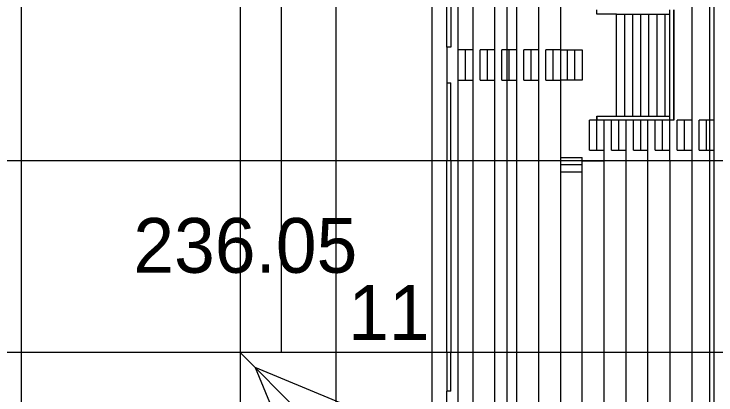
# Model space of a CAD drawing. Extents: x -264165 to -263575, y -1242333 to -1242036.
# Drawn here: x -263827.72 to -263802.08, y -1242218.43 to -1242204.52 of the extents above; entities that cross this region are included whole.
import ezdxf

# ---------------------------------------------------------------- set-up
doc = ezdxf.new("R2010")
doc.units = 0
for name, color, linetype in [('KFA_BODY_VYTYCOVAK', 7, 'Continuous'), ('KFA_HESCON_OSI_STAVBY', 7, 'Continuous'), ('KFA_SITUACIA_DRS_VYTYCOVAK_SEDA', 7, 'Continuous')]:
    doc.layers.add(name, color=color, linetype=linetype)

msp = doc.modelspace()

# ---------------------------------------------------------------- linework, layer by layer
at = {"layer": 'KFA_HESCON_OSI_STAVBY'}
for p, q in [((-263827.468, -1242080.447), (-263827.468, -1242248.737)), ((-263819.468, -1242080.447), (-263819.468, -1242248.737)), ((-263812.468, -1242080.447), (-263812.468, -1242248.737)), ((-263811.518, -1242080.447), (-263811.518, -1242248.737)), ((-263809.718, -1242080.447), (-263809.718, -1242248.737)), ((-263802.318, -1242080.447), (-263802.318, -1242248.737)), ((-263787.486, -1242209.882), (-263921.823, -1242209.882)), ((-263787.486, -1242216.882), (-263921.823, -1242216.882)), ((-263819.468, -1242216.882), (-263819.468, -1242216.882)), ((-263819.468, -1242216.882), (-263794.893, -1242241.457)), ((-263794.893, -1242227.382), (-263818.92, -1242217.43)), ((-263818.92, -1242217.43), (-263808.968, -1242241.457))]:
    msp.add_line(p, q, dxfattribs=at)
at = {"layer": 'KFA_SITUACIA_DRS_VYTYCOVAK_SEDA'}
for p, q in [((-263815.968, -1242108.382), (-263815.968, -1242220.382)), ((-263817.968, -1242111.882), (-263817.968, -1242216.882)), ((-263811.918, -1242205.732), (-263811.918, -1242202.882)), ((-263811.918, -1242205.732), (-263811.918, -1242202.882)), ((-263811.768, -1242202.882), (-263811.768, -1242205.732)), ((-263811.768, -1242202.882), (-263811.768, -1242205.732)), ((-263810.968, -1242202.882), (-263810.968, -1242209.882)), ((-263810.968, -1242202.882), (-263810.968, -1242209.882)), ((-263810.168, -1242202.882), (-263810.168, -1242209.882)), ((-263810.168, -1242202.882), (-263810.168, -1242209.882)), ((-263809.368, -1242202.882), (-263809.368, -1242209.882)), ((-263809.368, -1242202.882), (-263809.368, -1242209.882)), ((-263808.568, -1242202.882), (-263808.568, -1242209.882)), ((-263808.568, -1242202.882), (-263808.568, -1242209.882)), ((-263807.768, -1242202.882), (-263807.768, -1242209.882)), ((-263807.768, -1242202.882), (-263807.768, -1242209.882)), ((-263802.968, -1242202.882), (-263802.968, -1242209.882)), ((-263802.968, -1242202.882), (-263802.968, -1242209.882)), ((-263802.168, -1242202.882), (-263802.168, -1242209.882)), ((-263802.168, -1242202.882), (-263802.168, -1242209.882)), ((-263807.768, -1242203.003), (-263807.768, -1242205.832)), ((-263807.768, -1242203.003), (-263807.768, -1242205.832)), ((-263806.434, -1242204.52), (-263806.434, -1242204.37)), ((-263806.434, -1242204.52), (-263806.434, -1242204.37)), ((-263803.768, -1242208.394), (-263803.768, -1242204.369)), ((-263803.768, -1242208.394), (-263803.768, -1242204.369)), ((-263803.618, -1242208.394), (-263803.618, -1242204.369)), ((-263803.618, -1242208.394), (-263803.618, -1242204.369)), ((-263803.618, -1242204.369), (-263803.618, -1242208.394)), ((-263803.618, -1242204.369), (-263803.618, -1242208.394)), ((-263805.723, -1242204.52), (-263806.434, -1242204.52)), ((-263805.723, -1242204.52), (-263806.434, -1242204.52)), ((-263805.723, -1242208.245), (-263805.723, -1242204.52)), ((-263805.723, -1242208.245), (-263805.723, -1242204.52)), ((-263805.723, -1242204.52), (-263805.428, -1242204.52)), ((-263805.723, -1242204.52), (-263805.428, -1242204.52)), ((-263805.428, -1242204.52), (-263805.428, -1242208.245)), ((-263805.428, -1242204.52), (-263805.428, -1242208.245)), ((-263805.428, -1242204.52), (-263805.133, -1242204.52)), ((-263805.428, -1242204.52), (-263805.133, -1242204.52)), ((-263805.133, -1242204.52), (-263804.838, -1242204.52)), ((-263805.133, -1242204.52), (-263804.838, -1242204.52)), ((-263805.133, -1242204.52), (-263805.133, -1242208.245)), ((-263805.133, -1242204.52), (-263805.133, -1242208.245)), ((-263804.838, -1242204.52), (-263804.838, -1242208.245)), ((-263804.838, -1242204.52), (-263804.838, -1242208.245)), ((-263804.838, -1242204.52), (-263804.543, -1242204.52)), ((-263804.838, -1242204.52), (-263804.543, -1242204.52)), ((-263804.543, -1242204.52), (-263804.248, -1242204.52)), ((-263804.543, -1242204.52), (-263804.248, -1242204.52)), ((-263804.543, -1242204.52), (-263804.543, -1242208.245)), ((-263804.543, -1242204.52), (-263804.543, -1242208.245)), ((-263804.248, -1242204.52), (-263804.248, -1242208.245)), ((-263804.248, -1242204.52), (-263804.248, -1242208.245)), ((-263804.248, -1242204.52), (-263803.953, -1242204.52)), ((-263804.248, -1242204.52), (-263803.953, -1242204.52)), ((-263803.953, -1242204.52), (-263803.768, -1242204.52)), ((-263803.953, -1242204.52), (-263803.768, -1242204.52)), ((-263803.953, -1242204.52), (-263803.953, -1242208.245)), ((-263803.953, -1242204.52), (-263803.953, -1242208.245)), ((-263811.918, -1242205.732), (-263811.918, -1242207.032)), ((-263811.918, -1242205.732), (-263811.918, -1242207.032)), ((-263811.768, -1242205.732), (-263811.918, -1242205.732)), ((-263811.768, -1242205.732), (-263811.918, -1242205.732)), ((-263811.501, -1242206.932), (-263811.501, -1242205.832)), ((-263811.501, -1242206.932), (-263811.501, -1242205.832)), ((-263811.234, -1242205.832), (-263811.501, -1242205.832)), ((-263811.234, -1242205.832), (-263811.501, -1242205.832)), ((-263811.234, -1242206.932), (-263811.234, -1242205.832)), ((-263811.234, -1242206.932), (-263811.234, -1242205.832)), ((-263810.968, -1242205.832), (-263811.234, -1242205.832)), ((-263810.968, -1242205.832), (-263811.234, -1242205.832)), ((-263810.701, -1242206.932), (-263810.701, -1242205.832)), ((-263810.701, -1242206.932), (-263810.701, -1242205.832)), ((-263810.434, -1242205.832), (-263810.701, -1242205.832)), ((-263810.434, -1242205.832), (-263810.701, -1242205.832)), ((-263810.434, -1242206.932), (-263810.434, -1242205.832)), ((-263810.434, -1242206.932), (-263810.434, -1242205.832)), ((-263810.168, -1242205.832), (-263810.434, -1242205.832)), ((-263810.168, -1242205.832), (-263810.434, -1242205.832)), ((-263809.901, -1242206.932), (-263809.901, -1242205.832)), ((-263809.901, -1242206.932), (-263809.901, -1242205.832)), ((-263809.634, -1242205.832), (-263809.901, -1242205.832)), ((-263809.634, -1242205.832), (-263809.901, -1242205.832)), ((-263809.634, -1242206.932), (-263809.634, -1242205.832)), ((-263809.634, -1242206.932), (-263809.634, -1242205.832)), ((-263809.368, -1242205.832), (-263809.634, -1242205.832)), ((-263809.368, -1242205.832), (-263809.634, -1242205.832)), ((-263809.101, -1242206.932), (-263809.101, -1242205.832)), ((-263809.101, -1242206.932), (-263809.101, -1242205.832)), ((-263808.834, -1242205.832), (-263809.101, -1242205.832)), ((-263808.834, -1242205.832), (-263809.101, -1242205.832)), ((-263808.834, -1242206.932), (-263808.834, -1242205.832)), ((-263808.834, -1242206.932), (-263808.834, -1242205.832)), ((-263808.568, -1242205.832), (-263808.834, -1242205.832)), ((-263808.568, -1242205.832), (-263808.834, -1242205.832)), ((-263808.301, -1242206.932), (-263808.301, -1242205.832)), ((-263808.301, -1242206.932), (-263808.301, -1242205.832)), ((-263808.034, -1242205.832), (-263808.301, -1242205.832)), ((-263808.034, -1242205.832), (-263808.301, -1242205.832)), ((-263808.034, -1242206.932), (-263808.034, -1242205.832)), ((-263808.034, -1242206.932), (-263808.034, -1242205.832)), ((-263807.768, -1242205.832), (-263808.034, -1242205.832)), ((-263807.768, -1242205.832), (-263808.034, -1242205.832)), ((-263807.768, -1242205.832), (-263806.968, -1242205.832)), ((-263807.768, -1242205.832), (-263806.968, -1242205.832)), ((-263807.501, -1242206.932), (-263807.501, -1242205.832)), ((-263807.501, -1242206.932), (-263807.501, -1242205.832)), ((-263807.234, -1242206.932), (-263807.234, -1242205.832)), ((-263807.234, -1242206.932), (-263807.234, -1242205.832)), ((-263806.968, -1242205.832), (-263806.968, -1242206.932)), ((-263806.968, -1242205.832), (-263806.968, -1242206.932)), ((-263811.501, -1242206.932), (-263811.234, -1242206.932)), ((-263811.501, -1242206.932), (-263811.234, -1242206.932)), ((-263811.234, -1242206.932), (-263810.968, -1242206.932)), ((-263811.234, -1242206.932), (-263810.968, -1242206.932)), ((-263810.701, -1242206.932), (-263810.434, -1242206.932)), ((-263810.701, -1242206.932), (-263810.434, -1242206.932)), ((-263810.434, -1242206.932), (-263810.168, -1242206.932)), ((-263810.434, -1242206.932), (-263810.168, -1242206.932)), ((-263809.901, -1242206.932), (-263809.634, -1242206.932)), ((-263809.901, -1242206.932), (-263809.634, -1242206.932)), ((-263809.634, -1242206.932), (-263809.368, -1242206.932)), ((-263809.634, -1242206.932), (-263809.368, -1242206.932)), ((-263809.101, -1242206.932), (-263808.834, -1242206.932)), ((-263809.101, -1242206.932), (-263808.834, -1242206.932)), ((-263808.834, -1242206.932), (-263808.568, -1242206.932)), ((-263808.834, -1242206.932), (-263808.568, -1242206.932)), ((-263808.301, -1242206.932), (-263808.034, -1242206.932)), ((-263808.301, -1242206.932), (-263808.034, -1242206.932)), ((-263808.034, -1242206.932), (-263807.768, -1242206.932)), ((-263808.034, -1242206.932), (-263807.768, -1242206.932)), ((-263807.768, -1242206.932), (-263807.768, -1242209.761)), ((-263807.768, -1242206.932), (-263807.768, -1242209.761)), ((-263806.968, -1242206.932), (-263807.768, -1242206.932)), ((-263806.968, -1242206.932), (-263807.768, -1242206.932)), ((-263811.918, -1242207.032), (-263811.768, -1242207.032)), ((-263811.918, -1242207.032), (-263811.768, -1242207.032)), ((-263811.918, -1242207.032), (-263811.918, -1242209.882)), ((-263811.918, -1242207.032), (-263811.918, -1242209.882)), ((-263811.768, -1242209.882), (-263811.768, -1242207.032)), ((-263811.768, -1242209.882), (-263811.768, -1242207.032)), ((-263806.434, -1242208.394), (-263806.434, -1242208.244)), ((-263806.434, -1242208.394), (-263806.434, -1242208.244)), ((-263806.434, -1242208.244), (-263803.768, -1242208.244)), ((-263806.434, -1242208.244), (-263803.768, -1242208.244)), ((-263806.434, -1242208.245), (-263806.434, -1242208.395)), ((-263806.434, -1242208.245), (-263806.434, -1242208.395)), ((-263803.768, -1242208.394), (-263803.768, -1242208.244)), ((-263803.768, -1242208.394), (-263803.768, -1242208.244)), ((-263806.701, -1242209.494), (-263806.701, -1242208.394)), ((-263806.701, -1242209.494), (-263806.701, -1242208.394)), ((-263806.434, -1242208.394), (-263806.701, -1242208.394)), ((-263806.434, -1242208.394), (-263806.701, -1242208.394)), ((-263806.434, -1242209.494), (-263806.434, -1242208.394)), ((-263806.434, -1242209.494), (-263806.434, -1242208.394)), ((-263803.768, -1242208.394), (-263806.434, -1242208.394)), ((-263803.768, -1242208.394), (-263806.434, -1242208.394)), ((-263806.168, -1242209.882), (-263806.168, -1242208.394)), ((-263806.168, -1242209.882), (-263806.168, -1242208.394)), ((-263806.168, -1242209.882), (-263806.168, -1242208.394)), ((-263806.168, -1242209.882), (-263806.168, -1242208.394)), ((-263805.901, -1242209.494), (-263805.901, -1242208.394)), ((-263805.901, -1242209.494), (-263805.901, -1242208.394)), ((-263805.634, -1242209.494), (-263805.634, -1242208.394)), ((-263805.634, -1242209.494), (-263805.634, -1242208.394)), ((-263805.368, -1242209.882), (-263805.368, -1242208.394)), ((-263805.368, -1242209.882), (-263805.368, -1242208.394)), ((-263805.101, -1242209.494), (-263805.101, -1242208.394)), ((-263805.101, -1242209.494), (-263805.101, -1242208.394)), ((-263804.834, -1242209.494), (-263804.834, -1242208.394)), ((-263804.834, -1242209.494), (-263804.834, -1242208.394)), ((-263804.568, -1242209.882), (-263804.568, -1242208.394)), ((-263804.568, -1242209.882), (-263804.568, -1242208.394)), ((-263804.301, -1242209.494), (-263804.301, -1242208.394)), ((-263804.301, -1242209.494), (-263804.301, -1242208.394)), ((-263804.034, -1242209.494), (-263804.034, -1242208.394)), ((-263804.034, -1242209.494), (-263804.034, -1242208.394)), ((-263803.768, -1242209.882), (-263803.768, -1242208.394)), ((-263803.768, -1242209.882), (-263803.768, -1242208.394)), ((-263803.618, -1242208.394), (-263803.768, -1242208.394)), ((-263803.618, -1242208.394), (-263803.768, -1242208.394)), ((-263803.501, -1242209.494), (-263803.501, -1242208.394)), ((-263803.501, -1242209.494), (-263803.501, -1242208.394)), ((-263803.234, -1242208.394), (-263803.501, -1242208.394)), ((-263803.234, -1242208.394), (-263803.501, -1242208.394)), ((-263803.234, -1242209.494), (-263803.234, -1242208.394)), ((-263803.234, -1242209.494), (-263803.234, -1242208.394)), ((-263802.968, -1242208.394), (-263803.234, -1242208.394)), ((-263802.968, -1242208.394), (-263803.234, -1242208.394)), ((-263802.701, -1242209.494), (-263802.701, -1242208.394)), ((-263802.701, -1242209.494), (-263802.701, -1242208.394)), ((-263802.434, -1242208.394), (-263802.701, -1242208.394)), ((-263802.434, -1242208.394), (-263802.701, -1242208.394)), ((-263802.434, -1242209.494), (-263802.434, -1242208.394)), ((-263802.434, -1242209.494), (-263802.434, -1242208.394)), ((-263802.168, -1242208.394), (-263802.434, -1242208.394)), ((-263802.168, -1242208.394), (-263802.434, -1242208.394)), ((-263806.701, -1242209.494), (-263806.434, -1242209.494)), ((-263806.701, -1242209.494), (-263806.434, -1242209.494)), ((-263806.434, -1242209.494), (-263806.168, -1242209.494)), ((-263806.434, -1242209.494), (-263806.168, -1242209.494)), ((-263805.901, -1242209.494), (-263805.634, -1242209.494)), ((-263805.901, -1242209.494), (-263805.634, -1242209.494)), ((-263805.634, -1242209.494), (-263805.368, -1242209.494)), ((-263805.634, -1242209.494), (-263805.368, -1242209.494)), ((-263805.101, -1242209.494), (-263804.834, -1242209.494)), ((-263805.101, -1242209.494), (-263804.834, -1242209.494)), ((-263804.834, -1242209.494), (-263804.568, -1242209.494)), ((-263804.834, -1242209.494), (-263804.568, -1242209.494)), ((-263804.301, -1242209.494), (-263804.034, -1242209.494)), ((-263804.301, -1242209.494), (-263804.034, -1242209.494)), ((-263804.034, -1242209.494), (-263803.768, -1242209.494)), ((-263804.034, -1242209.494), (-263803.768, -1242209.494)), ((-263803.501, -1242209.494), (-263803.234, -1242209.494)), ((-263803.501, -1242209.494), (-263803.234, -1242209.494)), ((-263803.234, -1242209.494), (-263802.968, -1242209.494)), ((-263803.234, -1242209.494), (-263802.968, -1242209.494)), ((-263802.701, -1242209.494), (-263802.434, -1242209.494)), ((-263802.701, -1242209.494), (-263802.434, -1242209.494)), ((-263802.434, -1242209.494), (-263802.168, -1242209.494)), ((-263802.434, -1242209.494), (-263802.168, -1242209.494)), ((-263807.768, -1242209.761), (-263807.768, -1242210.028)), ((-263807.768, -1242209.761), (-263807.768, -1242210.028)), ((-263807.768, -1242209.761), (-263806.968, -1242209.761)), ((-263807.768, -1242209.761), (-263806.968, -1242209.761)), ((-263806.968, -1242209.882), (-263806.968, -1242209.761)), ((-263806.968, -1242209.882), (-263806.968, -1242209.761)), ((-263811.918, -1242216.882), (-263811.918, -1242209.882)), ((-263811.918, -1242216.882), (-263811.918, -1242209.882)), ((-263811.768, -1242209.882), (-263811.768, -1242216.882)), ((-263811.768, -1242209.882), (-263811.768, -1242216.882)), ((-263810.968, -1242209.882), (-263810.968, -1242216.882)), ((-263810.968, -1242209.882), (-263810.968, -1242216.882)), ((-263810.168, -1242209.882), (-263810.168, -1242216.882)), ((-263810.168, -1242209.882), (-263810.168, -1242216.882)), ((-263809.368, -1242209.882), (-263809.368, -1242216.882)), ((-263809.368, -1242209.882), (-263809.368, -1242216.882)), ((-263808.568, -1242209.882), (-263808.568, -1242216.882)), ((-263808.568, -1242209.882), (-263808.568, -1242216.882)), ((-263807.768, -1242209.882), (-263807.768, -1242216.882)), ((-263807.768, -1242209.882), (-263807.768, -1242216.882)), ((-263807.768, -1242210.028), (-263807.768, -1242210.294)), ((-263807.768, -1242210.028), (-263807.768, -1242210.294)), ((-263806.968, -1242210.028), (-263807.768, -1242210.028)), ((-263806.968, -1242210.028), (-263807.768, -1242210.028)), ((-263806.168, -1242209.882), (-263806.968, -1242209.882)), ((-263806.168, -1242209.882), (-263806.968, -1242209.882)), ((-263806.968, -1242209.882), (-263806.168, -1242209.882)), ((-263806.968, -1242209.882), (-263806.168, -1242209.882)), ((-263806.968, -1242216.882), (-263806.968, -1242209.882)), ((-263806.968, -1242216.882), (-263806.968, -1242209.882)), ((-263806.168, -1242216.882), (-263806.168, -1242209.882)), ((-263806.168, -1242216.882), (-263806.168, -1242209.882)), ((-263805.368, -1242216.882), (-263805.368, -1242209.882)), ((-263805.368, -1242216.882), (-263805.368, -1242209.882)), ((-263804.568, -1242216.882), (-263804.568, -1242209.882)), ((-263804.568, -1242216.882), (-263804.568, -1242209.882)), ((-263803.768, -1242209.882), (-263803.768, -1242216.882)), ((-263803.768, -1242209.882), (-263803.768, -1242216.882)), ((-263802.968, -1242209.882), (-263802.968, -1242216.882)), ((-263802.968, -1242209.882), (-263802.968, -1242216.882)), ((-263802.168, -1242209.882), (-263802.168, -1242216.882)), ((-263802.168, -1242209.882), (-263802.168, -1242216.882)), ((-263806.968, -1242210.294), (-263807.768, -1242210.294)), ((-263806.968, -1242210.294), (-263807.768, -1242210.294)), ((-263817.968, -1242216.882), (-263885.968, -1242216.882)), ((-263811.918, -1242216.882), (-263811.918, -1242218.29)), ((-263811.918, -1242216.882), (-263811.918, -1242218.29)), ((-263811.768, -1242218.29), (-263811.768, -1242216.882)), ((-263811.768, -1242218.29), (-263811.768, -1242216.882)), ((-263810.968, -1242216.882), (-263810.968, -1242220.724)), ((-263810.968, -1242216.882), (-263810.968, -1242220.724)), ((-263810.168, -1242216.882), (-263810.168, -1242221.055)), ((-263810.168, -1242216.882), (-263810.168, -1242221.055)), ((-263809.368, -1242216.882), (-263809.368, -1242221.386)), ((-263809.368, -1242216.882), (-263809.368, -1242221.386)), ((-263808.568, -1242216.882), (-263808.568, -1242221.718)), ((-263808.568, -1242216.882), (-263808.568, -1242221.718)), ((-263807.768, -1242216.882), (-263807.768, -1242222.049)), ((-263807.768, -1242216.882), (-263807.768, -1242222.049)), ((-263806.968, -1242222.381), (-263806.968, -1242216.882)), ((-263806.968, -1242222.381), (-263806.968, -1242216.882)), ((-263806.168, -1242222.712), (-263806.168, -1242216.882)), ((-263806.168, -1242222.712), (-263806.168, -1242216.882)), ((-263805.368, -1242223.043), (-263805.368, -1242216.882)), ((-263805.368, -1242223.043), (-263805.368, -1242216.882)), ((-263804.568, -1242223.375), (-263804.568, -1242216.882)), ((-263804.568, -1242223.375), (-263804.568, -1242216.882)), ((-263803.768, -1242216.882), (-263803.768, -1242223.706)), ((-263803.768, -1242216.882), (-263803.768, -1242223.706)), ((-263802.968, -1242216.882), (-263802.968, -1242224.037)), ((-263802.968, -1242216.882), (-263802.968, -1242224.037)), ((-263802.168, -1242216.882), (-263802.168, -1242224.369)), ((-263802.168, -1242216.882), (-263802.168, -1242224.369)), ((-263811.918, -1242220.33), (-263811.918, -1242218.29)), ((-263811.918, -1242220.33), (-263811.918, -1242218.29)), ((-263811.768, -1242218.29), (-263811.918, -1242218.29)), ((-263811.768, -1242218.29), (-263811.918, -1242218.29))]:
    msp.add_line(p, q, dxfattribs=at)

# ---------------------------------------------------------------- texts
at = {"layer": 'KFA_BODY_VYTYCOVAK'}
for s, p in [('236.05', (-263823.365, -1242213.971)), ('11', (-263815.519, -1242216.421))]:
    msp.add_text(s, height=2, dxfattribs=at).set_placement(p)

doc.saveas('drawing.dxf')
